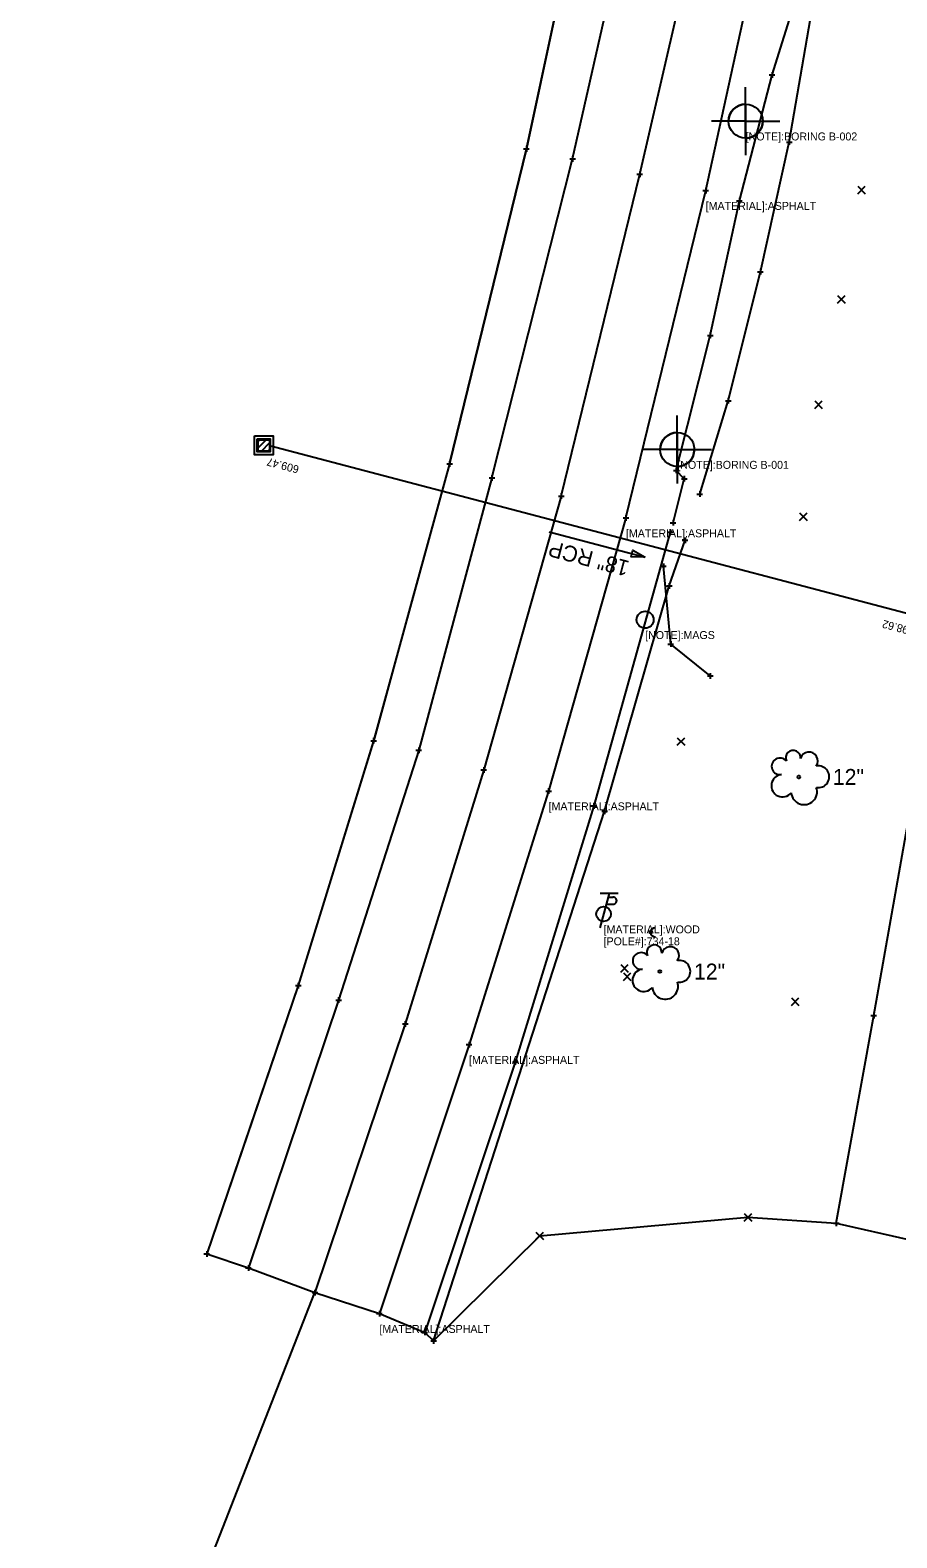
# Model space of a CAD drawing. Extents: x 1380627 to 1381920, y 503402 to 506786.
# Drawn here: x 1381601.9 to 1381754.6, y 504540.7 to 504806.3 of the extents above; entities that cross this region are included whole.
import ezdxf

# ---------------------------------------------------------------- set-up
doc = ezdxf.new("R2010")
doc.units = 0
for name, color, linetype in [('DR_X_Cells', 7, 'Continuous'), ('DR_X_Storm_Sewer', 7, 'Continuous'), ('DR_X_Text', 7, 'Continuous'), ('GE_X_Cells', 7, 'Continuous'), ('GK_Drainage_Nodes', 7, 'Continuous'), ('GT_Project_Soil_Boring', 7, 'Continuous'), ('PV_X_COP', 7, 'Continuous'), ('PV_X_EOP', 7, 'Continuous'), ('PV_X_Shoulder', 7, 'Continuous'), ('RD_X_GR_Rt', 7, 'Continuous'), ('SC_Scratch1', 7, 'Continuous'), ('SV_X_Control_Cells_Found_Text', 7, 'Continuous'), ('SV_X_Edge_of_Slip', 7, 'Continuous'), ('SV_X_Random_Point', 7, 'Continuous'), ('SV_X_Shot_Marker', 7, 'Continuous'), ('SV_X_Terrain_Boundary', 7, 'Continuous'), ('SV_X_Text', 7, 'Continuous'), ('SV_X_Toe_of_Slope', 7, 'Continuous'), ('UT_X_Misc_Cells', 7, 'Continuous'), ('VG_X_Cells', 7, 'Continuous'), ('VG_X_Text', 7, 'Continuous')]:
    doc.layers.add(name, color=color, linetype=linetype)

msp = doc.modelspace()

# ---------------------------------------------------------------- linework, layer by layer
at = {"layer": 'DR_X_Cells'}
for p, q in [((1381641.97, 504732.5), (1381643.73, 504734.26)), ((1381641.97, 504733.63), (1381642.59, 504734.26)), ((1381642.57, 504731.97), (1381644.26, 504733.66)), ((1381643.7, 504731.97), (1381644.26, 504732.53))]:
    msp.add_line(p, q, dxfattribs=at)
for points in [[(1381641.45, 504734.78), (1381644.78, 504734.78), (1381644.78, 504731.44), (1381641.45, 504731.44)], [(1381641.97, 504734.26), (1381644.26, 504734.26), (1381644.26, 504731.97), (1381641.97, 504731.97)], [(1381642.11, 504734.11), (1381644.11, 504734.11), (1381644.11, 504732.11), (1381642.11, 504732.11)]]:
    msp.add_lwpolyline(points, close=True, dxfattribs=at)
at = {"layer": 'DR_X_Storm_Sewer'}
msp.add_line((1381644.11, 504733.11), (1381758.39, 504703.01), dxfattribs=at)
at = {"layer": 'DR_X_Text'}
msp.add_line((1381693.41, 504717.9), (1381710.32, 504713.45), dxfattribs=at)
msp.add_lwpolyline([(1381710.32, 504713.45), (1381707.85, 504713.48), (1381708.15, 504714.64)], close=True, dxfattribs=at)
at = {"layer": 'GE_X_Cells'}
msp.add_circle((1381710.3, 504702.41), 1.5, dxfattribs=at)
at = {"layer": 'GK_Drainage_Nodes'}
for p, q in [((1381642.11, 504733.11), (1381642.11, 504733.11)), ((1381643.11, 504734.78), (1381643.11, 504734.78)), ((1381643.11, 504734.11), (1381643.11, 504734.11)), ((1381643.11, 504733.11), (1381643.11, 504733.11)), ((1381643.11, 504733.11), (1381643.11, 504733.11)), ((1381643.11, 504733.11), (1381643.11, 504733.11)), ((1381644.11, 504733.11), (1381644.11, 504733.11)), ((1381643.11, 504732.11), (1381643.11, 504732.11)), ((1381643.11, 504731.44), (1381643.11, 504731.44))]:
    msp.add_line(p, q, dxfattribs=at)
at = {"layer": 'GT_Project_Soil_Boring'}
for p, q in [((1381728.01, 504790.23), (1381728.01, 504796.23)), ((1381728.01, 504793.23), (1381728.01, 504790.23)), ((1381728.01, 504790.23), (1381722.01, 504790.23)), ((1381728.01, 504790.23), (1381725.01, 504790.23)), ((1381728.01, 504790.23), (1381728.01, 504784.23)), ((1381728.01, 504790.23), (1381734.01, 504790.23)), ((1381728.01, 504787.23), (1381728.01, 504790.23)), ((1381728.01, 504790.23), (1381731.01, 504790.23)), ((1381715.97, 504732.39), (1381715.97, 504738.39)), ((1381715.97, 504735.39), (1381715.97, 504732.39)), ((1381715.97, 504732.39), (1381709.97, 504732.39)), ((1381715.97, 504732.39), (1381712.97, 504732.39)), ((1381715.97, 504732.39), (1381715.97, 504726.39)), ((1381715.97, 504732.39), (1381721.97, 504732.39)), ((1381715.97, 504729.39), (1381715.97, 504732.39)), ((1381715.97, 504732.39), (1381718.97, 504732.39))]:
    msp.add_line(p, q, dxfattribs=at)
for centre in [(1381728.01, 504790.23), (1381715.97, 504732.39)]:
    msp.add_circle(centre, 3, dxfattribs=at)
for centre, start, end in [((1381728.01, 504790.23), 90, 180), ((1381728.01, 504790.23), 270, 360), ((1381715.97, 504732.39), 90, 180), ((1381715.97, 504732.39), 270, 360)]:
    msp.add_arc(centre, 3, start, end, dxfattribs=at)
at = {"layer": 'PV_X_COP'}
for p, q in [((1381695.51, 504724.18), (1381709.34, 504780.86)), ((1381601.95, 504455.65), (1381652.11, 504583.89))]:
    msp.add_line(p, q, dxfattribs=at)
for points in [[(1381709.34, 504780.86), (1381720.03, 504827.18), (1381728.71, 504873.89), (1381736.14, 504921.73), (1381742.06, 504966.83)], [(1381695.51, 504724.18), (1381681.86, 504675.95), (1381668.03, 504631.23), (1381652.11, 504583.89)]]:
    msp.add_lwpolyline(points, dxfattribs=at)
at = {"layer": 'PV_X_EOP'}
for p, q in [((1381683.3, 504727.39), (1381697.52, 504783.57)), ((1381706.92, 504720.33), (1381720.97, 504778))]:
    msp.add_line(p, q, dxfattribs=at)
for points in [[(1381697.52, 504783.57), (1381707.98, 504829.78), (1381716.73, 504876.36), (1381723.85, 504923.29), (1381729.83, 504968.85)], [(1381720.97, 504778), (1381731.18, 504824.5), (1381740.22, 504871.22), (1381748.22, 504920.18), (1381753.77, 504964.71)], [(1381683.3, 504727.39), (1381670.41, 504679.43), (1381656.3, 504635.42), (1381640.41, 504588.23)], [(1381706.92, 504720.33), (1381693.29, 504672.24), (1381679.27, 504627.58), (1381663.49, 504580.19)]]:
    msp.add_lwpolyline(points, dxfattribs=at)
at = {"layer": 'PV_X_Shoulder'}
msp.add_line((1381675.84, 504729.84), (1381689.39, 504785.35), dxfattribs=at)
for points in [[(1381689.39, 504785.35), (1381699.34, 504831.67), (1381707.97, 504878.35), (1381715.72, 504924.85), (1381722.16, 504970.19)], [(1381715.23, 504719.48), (1381717.19, 504727.23), (1381715.79, 504728.72), (1381721.76, 504752.5), (1381726.9, 504776.21), (1381732.66, 504798.37), (1381738.71, 504817.75), (1381739.85, 504824.31), (1381748.9, 504870.03), (1381756.24, 504918.38), (1381762.48, 504964.69)], [(1381675.84, 504729.84), (1381662.46, 504681.1), (1381649.19, 504637.96), (1381633.07, 504590.71)], [(1381714.73, 504717.85), (1381701.24, 504669.63), (1381687.41, 504624.49), (1381671.46, 504576.88)]]:
    msp.add_lwpolyline(points, dxfattribs=at)
at = {"layer": 'RD_X_GR_Rt'}
for points in [[(1381719.91, 504724.54), (1381724.94, 504740.97), (1381730.61, 504763.69), (1381735.7, 504786.53), (1381739.43, 504808.33), (1381742.29, 504825.57), (1381750.67, 504870.25), (1381758.18, 504916.55), (1381764.57, 504963.98)], [(1381673.04, 504575.38), (1381703.16, 504668.67), (1381714.55, 504708.37), (1381717.33, 504716.42)]]:
    msp.add_lwpolyline(points, dxfattribs=at)
at = {"layer": 'SV_X_Edge_of_Slip'}
msp.add_lwpolyline([(1381721.76, 504692.5), (1381714.8, 504698.12), (1381713.52, 504711.82)], dxfattribs=at)
at = {"layer": 'SV_X_Random_Point'}
for p, q in [((1381747.75, 504777.42), (1381749.08, 504778.76)), ((1381747.75, 504778.76), (1381749.08, 504777.42)), ((1381744.22, 504758.16), (1381745.55, 504759.5)), ((1381744.22, 504759.5), (1381745.55, 504758.16)), ((1381740.18, 504739.63), (1381741.51, 504740.97)), ((1381740.18, 504740.97), (1381741.51, 504739.63)), ((1381737.51, 504719.88), (1381738.85, 504721.22)), ((1381737.51, 504721.22), (1381738.85, 504719.88)), ((1381715.97, 504680.29), (1381717.3, 504681.63)), ((1381715.97, 504681.63), (1381717.3, 504680.29)), ((1381706, 504640.35), (1381707.33, 504641.68)), ((1381706, 504641.68), (1381707.33, 504640.35)), ((1381706.47, 504638.88), (1381707.8, 504640.21)), ((1381706.47, 504640.21), (1381707.8, 504638.88)), ((1381736.07, 504634.48), (1381737.4, 504635.81)), ((1381736.07, 504635.81), (1381737.4, 504634.48)), ((1381727.75, 504596.48), (1381729.09, 504597.82)), ((1381727.75, 504597.82), (1381729.09, 504596.48)), ((1381691.07, 504593.23), (1381692.41, 504594.56)), ((1381691.07, 504594.56), (1381692.41, 504593.23))]:
    msp.add_line(p, q, dxfattribs=at)
at = {"layer": 'SV_X_Shot_Marker'}
for p, q in [((1381732.16, 504798.37), (1381733.16, 504798.37)), ((1381732.66, 504798.87), (1381732.66, 504797.87)), ((1381732.66, 504798.37), (1381732.66, 504798.37)), ((1381735.2, 504786.53), (1381736.2, 504786.53)), ((1381735.7, 504787.03), (1381735.7, 504786.03)), ((1381735.7, 504786.53), (1381735.7, 504786.53)), ((1381688.89, 504785.35), (1381689.89, 504785.35)), ((1381689.39, 504785.85), (1381689.39, 504784.85)), ((1381689.39, 504785.35), (1381689.39, 504785.35)), ((1381697.02, 504783.57), (1381698.02, 504783.57)), ((1381697.52, 504784.07), (1381697.52, 504783.07)), ((1381697.52, 504783.57), (1381697.52, 504783.57)), ((1381708.84, 504780.86), (1381709.84, 504780.86)), ((1381709.34, 504781.36), (1381709.34, 504780.36)), ((1381709.34, 504780.86), (1381709.34, 504780.86)), ((1381720.97, 504778.5), (1381720.97, 504777.5)), ((1381720.47, 504778), (1381721.47, 504778)), ((1381720.97, 504778), (1381720.97, 504778)), ((1381726.4, 504776.21), (1381727.4, 504776.21)), ((1381726.9, 504776.71), (1381726.9, 504775.71)), ((1381726.9, 504776.21), (1381726.9, 504776.21)), ((1381730.11, 504763.69), (1381731.11, 504763.69)), ((1381730.61, 504764.19), (1381730.61, 504763.19)), ((1381730.61, 504763.69), (1381730.61, 504763.69)), ((1381721.26, 504752.5), (1381722.26, 504752.5)), ((1381721.76, 504753), (1381721.76, 504752)), ((1381721.76, 504752.5), (1381721.76, 504752.5)), ((1381724.44, 504740.97), (1381725.44, 504740.97)), ((1381724.94, 504741.47), (1381724.94, 504740.47)), ((1381724.94, 504740.97), (1381724.94, 504740.97)), ((1381675.84, 504730.34), (1381675.84, 504729.34)), ((1381675.34, 504729.84), (1381676.34, 504729.84)), ((1381675.84, 504729.84), (1381675.84, 504729.84)), ((1381683.3, 504727.89), (1381683.3, 504726.89)), ((1381715.29, 504728.72), (1381716.29, 504728.72)), ((1381715.79, 504729.22), (1381715.79, 504728.22)), ((1381715.79, 504728.72), (1381715.79, 504728.72)), ((1381717.19, 504727.73), (1381717.19, 504726.73)), ((1381682.8, 504727.39), (1381683.8, 504727.39)), ((1381683.3, 504727.39), (1381683.3, 504727.39)), ((1381716.69, 504727.23), (1381717.69, 504727.23)), ((1381717.19, 504727.23), (1381717.19, 504727.23)), ((1381719.91, 504725.04), (1381719.91, 504724.04)), ((1381695.01, 504724.18), (1381696.01, 504724.18)), ((1381695.51, 504724.68), (1381695.51, 504723.68)), ((1381695.51, 504724.18), (1381695.51, 504724.18)), ((1381719.41, 504724.54), (1381720.41, 504724.54)), ((1381719.91, 504724.54), (1381719.91, 504724.54)), ((1381706.42, 504720.33), (1381707.42, 504720.33)), ((1381706.92, 504720.83), (1381706.92, 504719.83)), ((1381706.92, 504720.33), (1381706.92, 504720.33)), ((1381715.23, 504719.98), (1381715.23, 504718.98)), ((1381714.23, 504717.85), (1381715.23, 504717.85)), ((1381714.73, 504719.48), (1381715.73, 504719.48)), ((1381714.73, 504718.35), (1381714.73, 504717.35)), ((1381714.73, 504717.85), (1381714.73, 504717.85)), ((1381715.23, 504719.48), (1381715.23, 504719.48)), ((1381716.83, 504716.42), (1381717.83, 504716.42)), ((1381717.33, 504716.92), (1381717.33, 504715.92)), ((1381717.33, 504716.42), (1381717.33, 504716.42)), ((1381713.02, 504711.82), (1381714.02, 504711.82)), ((1381713.52, 504712.32), (1381713.52, 504711.32)), ((1381713.52, 504711.82), (1381713.52, 504711.82)), ((1381714.05, 504708.37), (1381715.05, 504708.37)), ((1381714.55, 504708.87), (1381714.55, 504707.87)), ((1381714.55, 504708.37), (1381714.55, 504708.37)), ((1381714.8, 504698.62), (1381714.8, 504697.62)), ((1381714.3, 504698.12), (1381715.3, 504698.12)), ((1381714.8, 504698.12), (1381714.8, 504698.12)), ((1381721.26, 504692.5), (1381722.26, 504692.5)), ((1381721.76, 504693), (1381721.76, 504692)), ((1381721.76, 504692.5), (1381721.76, 504692.5)), ((1381661.96, 504681.1), (1381662.96, 504681.1)), ((1381662.46, 504681.6), (1381662.46, 504680.6)), ((1381662.46, 504681.1), (1381662.46, 504681.1)), ((1381670.41, 504679.93), (1381670.41, 504678.93)), ((1381669.91, 504679.43), (1381670.91, 504679.43)), ((1381670.41, 504679.43), (1381670.41, 504679.43)), ((1381681.36, 504675.95), (1381682.36, 504675.95)), ((1381681.86, 504676.45), (1381681.86, 504675.45)), ((1381681.86, 504675.95), (1381681.86, 504675.95)), ((1381692.79, 504672.24), (1381693.79, 504672.24)), ((1381693.29, 504672.74), (1381693.29, 504671.74)), ((1381693.29, 504672.24), (1381693.29, 504672.24)), ((1381700.74, 504669.63), (1381701.74, 504669.63)), ((1381701.24, 504670.13), (1381701.24, 504669.13)), ((1381701.24, 504669.63), (1381701.24, 504669.63)), ((1381703.16, 504669.17), (1381703.16, 504668.17)), ((1381702.66, 504668.67), (1381703.66, 504668.67)), ((1381703.16, 504668.67), (1381703.16, 504668.67)), ((1381648.69, 504637.96), (1381649.69, 504637.96)), ((1381649.19, 504638.46), (1381649.19, 504637.46)), ((1381649.19, 504637.96), (1381649.19, 504637.96)), ((1381655.8, 504635.42), (1381656.8, 504635.42)), ((1381656.3, 504635.92), (1381656.3, 504634.92)), ((1381656.3, 504635.42), (1381656.3, 504635.42)), ((1381750.08, 504632.7), (1381751.08, 504632.7)), ((1381750.58, 504633.2), (1381750.58, 504632.2)), ((1381750.58, 504632.7), (1381750.58, 504632.7)), ((1381667.53, 504631.23), (1381668.53, 504631.23)), ((1381668.03, 504631.73), (1381668.03, 504630.73)), ((1381668.03, 504631.23), (1381668.03, 504631.23)), ((1381678.77, 504627.58), (1381679.77, 504627.58)), ((1381679.27, 504628.08), (1381679.27, 504627.08)), ((1381679.27, 504627.58), (1381679.27, 504627.58)), ((1381686.91, 504624.49), (1381687.91, 504624.49)), ((1381687.41, 504624.99), (1381687.41, 504623.99)), ((1381687.41, 504624.49), (1381687.41, 504624.49)), ((1381743.47, 504596.11), (1381744.47, 504596.11)), ((1381743.97, 504596.61), (1381743.97, 504595.61)), ((1381743.97, 504596.11), (1381743.97, 504596.11)), ((1381632.57, 504590.71), (1381633.57, 504590.71)), ((1381633.07, 504591.21), (1381633.07, 504590.21)), ((1381633.07, 504590.71), (1381633.07, 504590.71)), ((1381639.91, 504588.23), (1381640.91, 504588.23)), ((1381640.41, 504588.73), (1381640.41, 504587.73)), ((1381640.41, 504588.23), (1381640.41, 504588.23)), ((1381652.11, 504584.39), (1381652.11, 504583.39)), ((1381651.61, 504583.89), (1381652.61, 504583.89)), ((1381652.11, 504583.89), (1381652.11, 504583.89)), ((1381662.99, 504580.19), (1381663.99, 504580.19)), ((1381663.49, 504580.69), (1381663.49, 504579.69)), ((1381663.49, 504580.19), (1381663.49, 504580.19)), ((1381670.96, 504576.88), (1381671.96, 504576.88)), ((1381671.46, 504577.38), (1381671.46, 504576.38)), ((1381671.46, 504576.88), (1381671.46, 504576.88)), ((1381672.54, 504575.38), (1381673.54, 504575.38)), ((1381673.04, 504575.88), (1381673.04, 504574.88)), ((1381673.04, 504575.38), (1381673.04, 504575.38))]:
    msp.add_line(p, q, dxfattribs=at)
at = {"layer": 'SV_X_Terrain_Boundary'}
for points in [[(1381633.07, 504590.71), (1381640.41, 504588.23), (1381652.11, 504583.89), (1381663.49, 504580.19), (1381671.46, 504576.88), (1381673.04, 504575.38), (1381691.74, 504593.89), (1381728.42, 504597.15), (1381743.97, 504596.11), (1381756.96, 504593.19), (1381809.7, 504557.46), (1381859.78, 504551.94), (1381857.29, 504586.1), (1381880.18, 504630.82), (1381903.11, 504693.5), (1381902.57, 504736.65), (1381902.08, 504783.53), (1381912.66, 504838.51)], [(1381694.64, 504809.79), (1381689.39, 504785.35), (1381675.84, 504729.84), (1381669.22, 504705.74), (1381662.61, 504681.63), (1381649.19, 504637.96), (1381641.12, 504614.3), (1381633.07, 504590.71)]]:
    msp.add_lwpolyline(points, dxfattribs=at)
at = {"layer": 'SV_X_Toe_of_Slope'}
msp.add_lwpolyline([(1381743.97, 504596.11), (1381750.58, 504632.7), (1381758.24, 504675.79), (1381761.89, 504691.85)], dxfattribs=at)
at = {"layer": 'UT_X_Misc_Cells'}
for p, q in [((1381703.95, 504654.17), (1381702.34, 504648.17)), ((1381705.55, 504654.17), (1381702.35, 504654.17)), ((1381703.79, 504653.57), (1381704.64, 504653.57)), ((1381703.44, 504652.29), (1381704.64, 504652.29))]:
    msp.add_line(p, q, dxfattribs=at)
for centre, radius in [((1381702.98, 504650.57), 1.3), ((1381711.27, 504647.34), 0.2)]:
    msp.add_circle(centre, radius, dxfattribs=at)
for centre, radius, start, end in [((1381704.65, 504652.93), 0.638, 268.8767, 91.1233), ((1381712.07, 504647.34), 0.8, 90, 270)]:
    msp.add_arc(centre, radius, start, end, dxfattribs=at)
at = {"layer": 'VG_X_Cells'}
for centre in [(1381737.37, 504674.71), (1381712.9, 504640.44)]:
    msp.add_circle(centre, 0.24, dxfattribs=at)
for centre, radius, start, end in [((1381734.06, 504676.58), 1.47, 39.0625, 279.5412), ((1381736.38, 504678.08), 1.32, 354.0047, 205.9741), ((1381739.19, 504677.54), 1.55, 323.83, 165.0376), ((1381734.51, 504673.17), 1.97, 96.1722, 320.5737), ((1381740.83, 504674.75), 1.91, 259.1453, 101.4596), ((1381738.31, 504672.11), 2.28, 184.9476, 19.4572), ((1381709.59, 504642.31), 1.47, 39.0625, 279.5412), ((1381711.91, 504643.81), 1.32, 354.0047, 205.9741), ((1381714.72, 504643.27), 1.55, 323.83, 165.0376), ((1381710.04, 504638.89), 1.97, 96.1722, 320.5737), ((1381716.36, 504640.48), 1.91, 259.1453, 101.4596), ((1381713.84, 504637.84), 2.28, 184.9476, 19.4572)]:
    msp.add_arc(centre, radius, start, end, dxfattribs=at)

# ---------------------------------------------------------------- texts
at = {"layer": 'DR_X_Text'}
msp.add_text('18" RCP', height=2.8, rotation=165.2421, dxfattribs=at).set_placement((1381707.7, 504712.69))
at = {"layer": 'SC_Scratch1'}
for s, p in [('609.47', (1381649.42, 504729.49)), ('598.62', (1381757.84, 504700.93))]:
    msp.add_text(s, height=1.4, rotation=165.2421, dxfattribs=at).set_placement(p)
at = {"layer": 'SV_X_Control_Cells_Found_Text'}
msp.add_text('[NOTE]:MAGS', height=1.4, dxfattribs=at).set_placement((1381710.3, 504699.01))
at = {"layer": 'SV_X_Text'}
for s, p in [('[NOTE]:BORING B-002', (1381728.01, 504786.83)), ('[MATERIAL]:ASPHALT', (1381720.97, 504774.6)), ('[NOTE]:BORING B-001', (1381715.97, 504728.99)), ('[MATERIAL]:ASPHALT', (1381706.92, 504716.93)), ('[MATERIAL]:ASPHALT', (1381693.29, 504668.84)), ('[MATERIAL]:WOOD', (1381702.98, 504647.17)), ('[POLE#]:734-18', (1381702.98, 504645.07)), ('[MATERIAL]:ASPHALT', (1381679.27, 504624.18)), ('[MATERIAL]:ASPHALT', (1381663.49, 504576.79))]:
    msp.add_text(s, height=1.4, dxfattribs=at).set_placement(p)
at = {"layer": 'VG_X_Text'}
for p in [(1381743.37, 504673.32), (1381718.9, 504639.04)]:
    msp.add_text('12"', height=2.8, dxfattribs=at).set_placement(p)

doc.saveas('drawing.dxf')
